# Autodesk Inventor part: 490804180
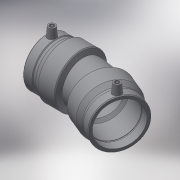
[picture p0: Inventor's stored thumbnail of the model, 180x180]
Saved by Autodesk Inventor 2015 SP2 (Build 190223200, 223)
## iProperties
Created: 2017-06
Part Number: 490804180
Material: Generic
Description: PLASSON 22.5° ELBOW 180
Document SubType Name: Modeling
Designer: KIM
Mass: 55.0731 g
Surface Area: 148.067 cm^2
Volume: 55.0731 cm^3
Density: 1 g/cm^3
Appearance: Default
Author: KIM
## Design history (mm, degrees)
derived "490804.ipt"
feature "Solid1::490804.ipt"
tag "TaggingFeature1"
body "Solid1"
other parameters: "d14" = 17.6296, "d19" = 3.52592, "d20" = 168 deg, "d22" = 224.48, "d23" = 244, "d24" = 217.7456, "d29" = 115, "d35" = 15, "d39" = 5 deg, "d45" = 4, "d46" = 14, "d47" = 0, "d67" = 45 deg, "d71" = 157.5 deg, "d75" = 12.2, "d82" = 45 deg, "d83" = 105, "d84" = 219.6, "d94" = 157.5 deg, "d95" = 108.8728, "d98" = 391, "d99" = 117.3, "d105" = 30.45, "d106" = 7.6125, "L_" = 391, "L_1" = 105, "D_" = 244, "A_" = 115, "d_2" = 12
